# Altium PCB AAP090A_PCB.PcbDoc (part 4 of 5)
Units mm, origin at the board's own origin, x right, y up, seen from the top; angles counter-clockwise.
Board outline 160 x 130 mm, 4 copper layers (Top Layer, Signal Layer 1, Signal Layer 2, Bottom Layer), stack 1.567 mm thick; 507 components, 275 nets, 1462 pads, 1041 vias.
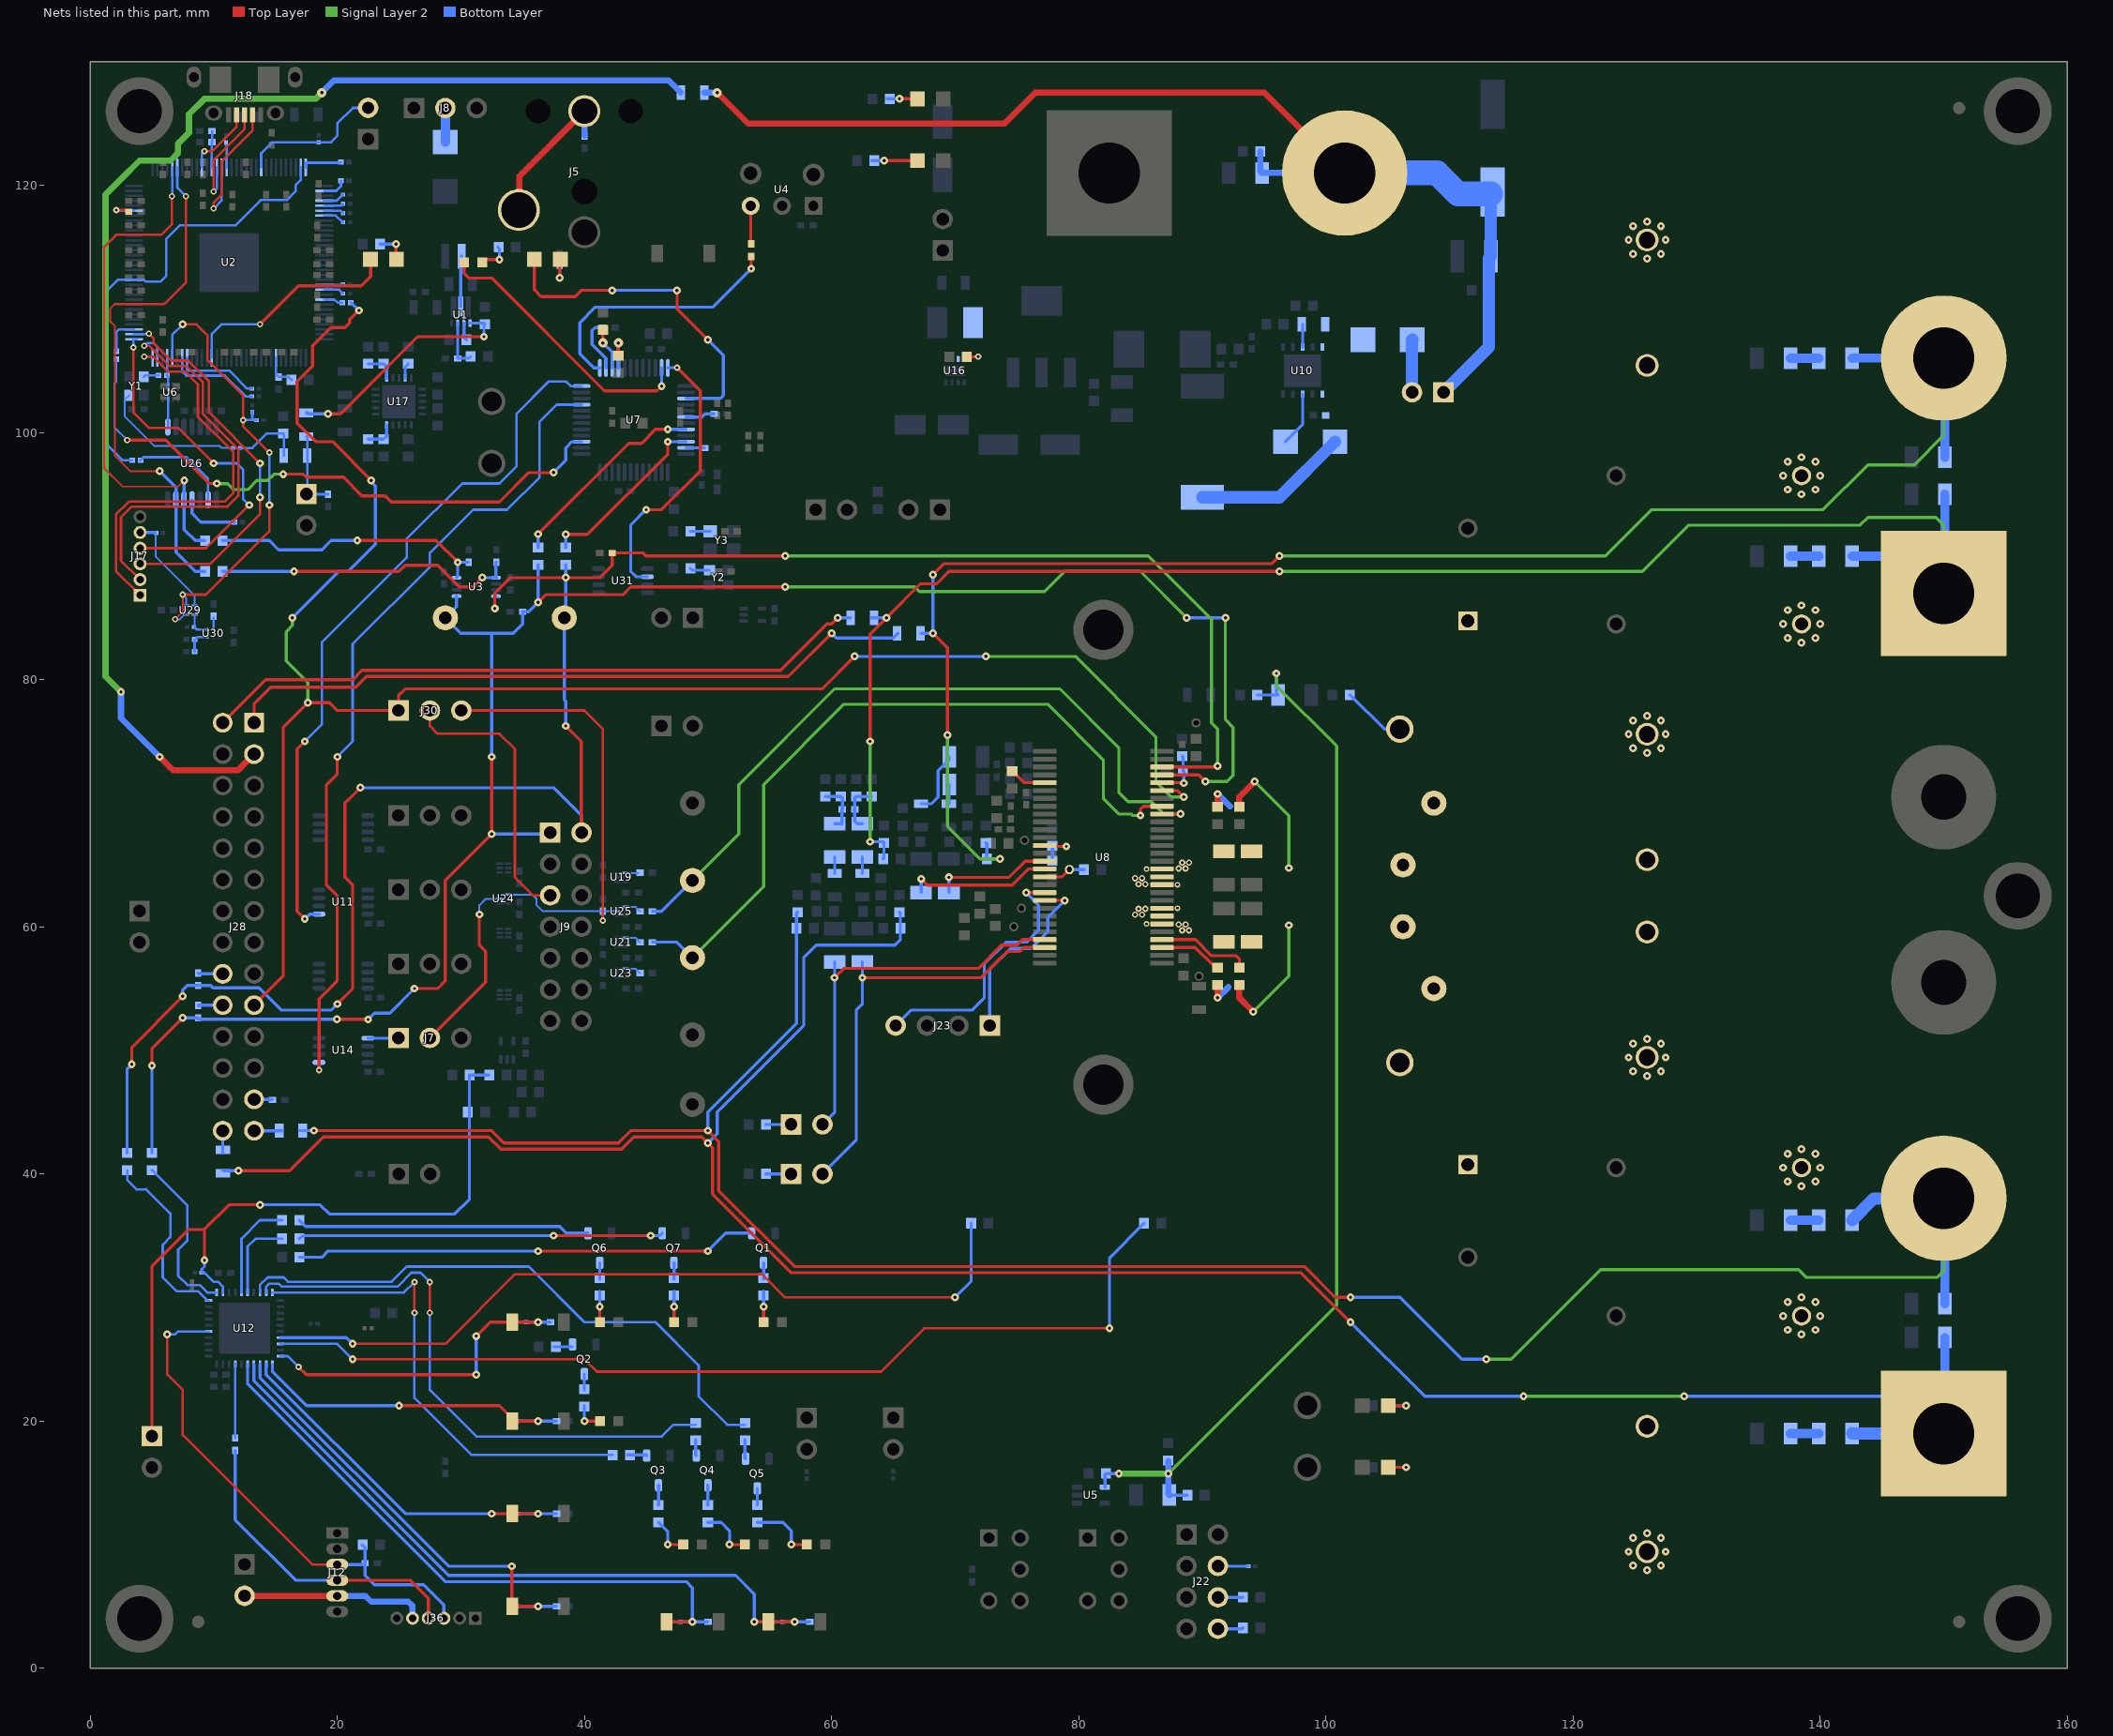
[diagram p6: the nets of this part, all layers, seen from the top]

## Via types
v1: diameter 0.635, hole 0.254, Top Layer to Bottom Layer, tented both sides, 653 vias
v2: diameter 0.508, hole 0.254, Top Layer to Bottom Layer, tented both sides, 340 vias
v3: diameter 0.5, hole 0.2, Top Layer to Bottom Layer, 24 vias
v4: diameter 0.6, hole 0.3, Top Layer to Bottom Layer, 12 vias
v5: diameter 0.762, hole 0.254, Top Layer to Bottom Layer, tented both sides, 8 vias
v6: diameter 0.457, hole 0.203, Top Layer to Bottom Layer, tented both sides, 4 vias

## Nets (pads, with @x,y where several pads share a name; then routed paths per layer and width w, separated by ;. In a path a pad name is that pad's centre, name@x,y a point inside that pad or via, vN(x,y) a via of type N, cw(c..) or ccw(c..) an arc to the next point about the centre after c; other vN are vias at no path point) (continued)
NetC76_2: C76.2 U8.32 | length 7.7
  Top Layer w0.25: U8.32@86.75,58.957 89.443,58.957 90.75,57.65 92.75,57.65 93,57.4 C76.2@93,56.6
NetC77_2: C77.2 U8.31 | length 5
  Top Layer w0.25: U8.31@86.75,58.322 89.427,58.322 91,56.75 C77.2@91,56.65
NetC82_1: C82.1 R140.2 U2.103 | length 2.8
  Bottom Layer w0.2: U2.103@15.05,106.05 15.05,104.7 C82.1@15.25,104.5 16.05,104.5 R140.2@16.3,104.25
NetC95_2: C95.2 U17.19 | length 1.3
  Bottom Layer w0.2: U17.19@25.5,104.4 25.5,105.3 C95.2@25.75,105.55
NetC98_1: C98.1 R87.2 | length 2.3
  Bottom Layer w0.75: R87.2@137.6,106 C98.1@139.9,106
NetC103_1: C103.1 R89.2 | length 2.3
  Bottom Layer w0.75: R89.2@137.6,90 C103.1@139.9,90
NetC104_1: C104.1 R93.2 | length 2.3
  Bottom Layer w0.75: R93.2@137.6,36.25 C104.1@139.9,36.25
NetC105_1: C105.1 R94.2 | length 2.3
  Bottom Layer w0.75: R94.2@137.6,19 C105.1@139.9,19
NetC106_1: C106.1 R13.1 R59.2 R67.2 | length 4
  Bottom Layer w0.25: R13.1@62.5,68.35 62.1,68.35 61.875,68.575 C106.1@61.875,69.5 61.875,70.425 R67.2@62,70.55 R59.2@63.25,70.55
NetC106_2: C106.2 R30.1 R64.2 R69.2 | length 4.1
  Bottom Layer w0.25: R64.2@59.5,70.55 R69.2@60.75,70.55 60.875,70.425 C106.2@60.875,69.5 60.85,69.475 60.85,68.35 R30.1@60.25,68.35
NetC107_2: C107.2 U8.5 | length 2.8
  Top Layer w0.25: C107.2@74.75,72.5 75.593,71.657 U8.5@77.25,71.657
NetC150_2: C150.2 U30.5 | length 1
  Bottom Layer w0.2: U30.5@10,84.05 C150.2@10,85
NetD1_1: D1.1 R141.2 | length 2.6
  Top Layer w0.25: v1(24.75,115.25) 24.75,114.05 D1.1@24.8,114
  Bottom Layer w0.25: R141.2@23.45,115.25 v1(24.75,115.25)
NetD1_2: D1.2 U2.116 | length 18.1
  Top Layer w0.25: v2(13.75,108.75) 16.875,111.875 21.95,111.875 22.7,112.625 D1.2@22.7,114
  Bottom Layer w0.2: U2.116@9.85,106.05 9.85,107.975 10.625,108.75 v2(13.75,108.75)
NetD2_1: D2.1 R19.2 | length 2.5
  Top Layer w0.25: D2.1@31.75,113.75 32,114 v1(33.125,114)
  Bottom Layer w0.25: R19.2@33,115 33.125,114.875 v1(33.125,114)
NetD2_2: D2.2 U7.11 | length 22.6
  Top Layer w0.25: D2.2@30.25,113.75 30.25,112.875 30.625,112.5 32.5,112.5 41.625,103.375 45.875,103.375 v1(46.25,103.75) ; D2.2@30.25,114 D2.2@30.375,113.875
  Bottom Layer w0.25: v1(46.25,103.75) U7.11@46.25,105.225
NetD3_1: D3.1 R23.1 | length 2.5
  Top Layer w0.25: v1(38,112.5) 38,113.95 D3.1@38.05,114
  Bottom Layer w0.25: v1(38,112.5) R23.1@38,113.5
NetD3_2: D3.2 U7.15 | length 27.7
  Top Layer w0.25: D3.2@36,113.95 D3.2@35.95,114 35.95,111.55 36.5,111 39.25,111 39.75,111.5 v1(42.25,111.5) ; v1(47.5,111.5) 47.5,110 v1(50,107.5)
  Bottom Layer w0.25: v1(42.25,111.5) v1(47.5,111.5) ; U7.15@48.225,102.75 51,102.75 51.25,103 51.25,106.25 v1(50,107.5)
NetD4_2: D4.2 R46.1 | length 2.5
  Top Layer w0.25: v1(40,20) D4.2@41.25,20
  Bottom Layer w0.25: v1(40,20) R46.1@40,21.25
NetD5_2: D5.2 R47.1 | length 3.4
  Top Layer w0.25: v1(46.75,10) D5.2@48,10
  Bottom Layer w0.25: R47.1@46,11.8 46.75,11.05 v1(46.75,10)
NetD6_2: D6.2 R48.1 | length 4.4
  Top Layer w0.25: v1(51.75,10) D6.2@53,10
  Bottom Layer w0.25: R48.1@50,11.8 51.075,11.8 51.75,11.125 v1(51.75,10)
NetD7_2: D7.2 R49.1 | length 5.4
  Top Layer w0.25: v1(56.75,10) D7.2@58,10
  Bottom Layer w0.25: R49.1@54,11.8 56.075,11.8 56.75,11.125 v1(56.75,10)
NetD8_2: D8.2 R57.1 | length 2.5
  Top Layer w0.25: D8.2@41.25,28 v1(41.25,29.25)
  Bottom Layer w0.25: v1(41.25,29.25) R57.1@41.25,30.5
NetD9_1: D9.1 R78.1 | length 2.7
  Top Layer w0.25: D9.1@105.05,21.25 v1(106.5,21.25)
  Bottom Layer w0.25: R78.1@105.2,21.25 v1(106.5,21.25)
NetD10_1: D10.1 R79.1 | length 2.7
  Top Layer w0.25: D10.1@105.05,16.25 v1(106.5,16.25)
  Bottom Layer w0.25: R79.1@105.2,16.25 v1(106.5,16.25)
NetD11_2: D11.2 J26.2 | length 4.3
  Bottom Layer w1: J26.2@106.98,103.25 106.98,107.48 D11.2@107,107.5
NetD12_2: D12.2 U10.3 | length 4.4
  Bottom Layer w0.25: D12.2@96.75,99.25 98.125,100.625 U10.3@98.125,103.1
NetD13_2: D13.2 R85.1 | length 2.5
  Top Layer w0.25: v1(65.5,127) D13.2@66.95,127
  Bottom Layer w0.25: R85.1@64.5,127 v1(65.5,127)
NetD14_2: D14.2 R86.1 | length 3.7
  Top Layer w0.25: v1(64.25,122) D14.2@66.95,122
  Bottom Layer w0.25: R86.1@63.25,122 v1(64.25,122)
NetD15_2: D15.2 R108.1 | length 2.5
  Top Layer w0.25: D15.2@47.25,28 v1(47.25,29.25)
  Bottom Layer w0.25: v1(47.25,29.25) R108.1@47.25,30.5
NetD16_2: D16.2 R106.1 | length 2.5
  Top Layer w0.25: D16.2@54.5,28 v1(54.5,29.25)
  Bottom Layer w0.25: v1(54.5,29.25) R106.1@54.5,30.5
NetD17_2: D17.2 J8.2 | length 2.7
  Bottom Layer w0.75: D17.2@28.75,123.5 J8.2@28.75,126.25
NetJ5_1: J5.1 J5.4 L4.1 | length 11.9
  Top Layer w0.5: J5.4@34.75,118 34.75,120.75 J5.1@40,126
  Bottom Layer w0.5: L4.1@40,124 J5.1@40,125.75
NetJ11_2: J11.2 J12.5 J36.5 | length 14.9
  Top Layer w0.5: J11.2@12.5,5.855 12.51,5.845 J12.5@20,5.845
  Bottom Layer w0.5: J12.5@20,5.845 22.28,5.845 22.75,5.375 25.75,5.375 26.095,5.03 J36.5@26.095,4.04
NetJ22_4: J22.4 R77.2 | length 2.5
  Bottom Layer w0.25: J22.4@91.27,8.27 91.29,8.25 R77.2@93.72,8.25
NetJ22_6: J22.6 R76.2 | length 2
  Bottom Layer w0.25: J22.6@91.27,5.73 93.28,5.73 R76.2@93.3,5.75
NetJ22_8: J22.8 R75.2 | length 2.1
  Bottom Layer w0.25: J22.8@91.27,3.19 93.24,3.19 R75.2@93.3,3.25
NetJ28_25: J28.25 R123.1 | length 1.5
  Bottom Layer w0.25: J28.25@13.27,46.03 14.72,46.03 R123.1@14.75,46
NetJ31_1: J31.1 R99.2 | length 2
  Bottom Layer w0.25: R99.2@54.7,44 J31.1@56.73,44
NetJ32_1: J32.1 R100.2 | length 2
  Bottom Layer w0.25: R100.2@54.7,40 J32.1@56.73,40
NetJ33_1: J33.1 R80.2 R159.2 R164.1 | length 6.5
  Bottom Layer w0.2: J33.1@17.5,94.875 17.575,94.95 J33.1@17.575,95 ; R159.2@17.5,99.675 17.575,99.6 R164.1@17.575,98.125 J33.1@17.575,95 ; R80.2@19.25,95 J33.1@17.575,95
NetL1_1: L1.1 U1.6 | length 4.1
  Bottom Layer w0.25: U1.6@30,110.2 30,114.175 L1.1@30.075,114.25
NetQ1_1: Q1.1 R109.1 | length 37.4
  Top Layer w0.25: v1(36.25,33.75) v1(50,33.75)
  Bottom Layer w0.25: R109.1@16.95,33.25 18.75,33.25 19.25,33.75 v1(36.25,33.75) ; v1(50,33.75) 51.45,35.2 Q1.1@53.55,35.2
NetQ1_3: Q1.3 R106.2 | length 1.3
  Bottom Layer w0.25: R106.2@54.5,31.5 Q1.3@54.5,32.8
NetQ2_1: Q2.1 R50.1 | length 1.5
  Bottom Layer w0.25: R50.1@37.5,26 Q2.1@39,26
NetQ2_3: Q2.3 R46.2 | length 1.3
  Bottom Layer w0.25: R46.2@40,22.5 Q2.3@40,23.8
NetQ3_1: Q3.1 R51.1 | length 1.6
  Bottom Layer w0.25: R51.1@43.5,17.25 45,17.25 Q3.1@45.05,17.2
NetQ3_3: Q3.3 R47.2 | length 1.6
  Bottom Layer w0.25: R47.2@46,13.2 Q3.3@46,14.8
NetQ4_1: Q4.1 R52.1 | length 1.3
  Bottom Layer w0.25: R52.1@49,18.5 49,17.25 Q4.1@49.05,17.2
NetQ4_3: Q4.3 R48.2 | length 1.6
  Bottom Layer w0.25: R48.2@50,13.2 Q4.3@50,14.8
NetQ5_1: Q5.1 R53.1 | length 1.6
  Bottom Layer w0.25: R53.1@53,18.5 53,17 Q5.1@53.05,16.95
NetQ5_3: Q5.3 R49.2 | length 1.3
  Bottom Layer w0.25: R49.2@54,13.2 Q5.3@54,14.55
NetQ6_1: Q6.1 R105.1 | length 23.8
  Bottom Layer w0.25: R105.1@16.95,36.25 17.45,35.75 38,35.75 38.55,35.2 Q6.1@40.3,35.2
NetQ6_3: Q6.3 R57.2 | length 1.3
  Bottom Layer w0.25: R57.2@41.25,31.5 Q6.3@41.25,32.8
NetQ7_1: Q7.1 R107.1 | length 29.5
  Top Layer w0.25: v1(37.5,35) v1(45.375,35)
  Bottom Layer w0.25: R107.1@16.95,34.75 17.2,35 v1(37.5,35) ; v1(45.375,35) 46.1,35 Q7.1@46.3,35.2
NetQ7_3: Q7.3 R108.2 | length 1.3
  Bottom Layer w0.25: R108.2@47.25,31.5 Q7.3@47.25,32.8
NetR1_1: R1.1 R3.2 U1.3 | length 4
  Bottom Layer w0.2: U1.3@29.75,108.85 R1.1@29.75,106 30.65,106 R3.2@30.8,106.15
NetR2_1: R2.1 U1.2 | length 1.4
  Bottom Layer w0.25: U1.2@30.25,108.85 30.25,107.7 R2.1@30.45,107.5
NetR4_2: R4.2 U16.8 | length 2.1
  Top Layer w0.25: R4.2@71,106.125 v2(71.875,106.125)
  Bottom Layer w0.25: U16.8@70.75,105.95 71.2,105.95 71.375,106.125 v2(71.875,106.125)
NetR6_2: R6.2 R7.2 U17.16 | length 2.5
  Bottom Layer w0.25: R6.2@22.5,105.55 R7.2@23.75,105.55 24,105.3 U17.16@24,104.4
NetR8_2: R8.2 R9.2 U17.10 | length 2.5
  Bottom Layer w0.25: R8.2@22.5,99.45 R9.2@23.75,99.45 24,99.7 U17.10@24,100.6
NetR13_2: R13.2 R14.1 | length 1.3
  Bottom Layer w0.25: R14.1@62.5,64.325 R13.2@62.5,65.65
NetR16_1: R16.1 U4.3 | length 3.1
  Top Layer w0.25: U4.3@53.46,118.33 53.46,115.29 R16.1@53.5,115.25
NetR17_1: R17.1 U19.4 | length 1
  Bottom Layer w0.15: U19.4@43.34,64.35 44.35,64.35 R17.1@44.375,64.375
NetR18_1: R18.1 U21.4 | length 1.3
  Bottom Layer w0.15: U21.4@43.34,59.1 44.15,59.1 R18.1@44.5,58.75
NetR20_2: R20.2 U7.18 | length 2.4
  Bottom Layer w0.25: U7.18@48.225,101.25 49.5,101.25 49.75,101.5 R20.2@50.5,101.5
NetR21_1: R21.1 U23.4 | length 1.3
  Bottom Layer w0.15: U23.4@43.34,56.6 44.15,56.6 R21.1@44.5,56.25
NetR22_2: R22.2 U7.23 | length 1.5
  Bottom Layer w0.25: U7.23@48.225,98.75 R22.2@49.75,98.75
NetR24_1: R24.1 U25.4 | length 1.3
  Bottom Layer w0.15: U25.4@43.34,61.6 44.15,61.6 R24.1@44.5,61.25
NetR30_2: R30.2 R33.1 | length 1.3
  Bottom Layer w0.25: R33.1@60.25,64.325 R30.2@60.25,65.65
NetR34_2: R34.2 U10.8 | length 1.9
  Bottom Layer w0.25: U10.8@98.125,106.9 R34.2@98.125,108.75
NetR61_2: R61.2 R68.1 | length 5.2
  Bottom Layer w0.25: R68.1@67.25,69.95 68.075,69.95 68.625,70.5 68.625,72.625 69.525,73.525 R61.2@69.525,73.75
NetR63_2: R63.2 R159.1 U1.1 | length 19.2
  Top Layer w0.25: v1(19.25,101.5) 20.25,101.5 20.375,101.625 21.375,102.625 26.5,107.75 v1(31.875,107.75)
  Bottom Layer w0.2: v1(31.875,107.75) 31.875,108.675 R63.2@31.95,108.75
  Bottom Layer w0.25: R159.1@17.5,101.575 17.55,101.625 17.675,101.5 v1(19.25,101.5) ; U1.1@30.75,108.85 R63.2@31.85,108.85
NetR72_2: R72.2 R73.1 | length 1.6
  Bottom Layer w0.25: R73.1@69.5,69.95 69.525,69.975 R72.2@69.525,71.5
NetR83_2: R83.2 U2.88 | length 1.6
  Bottom Layer w0.2: U2.88@18.95,110.75 19.75,110.75 20.058,110.5 R83.2@20.42,110.5
NetR101_2: R101.2 R102.2 U8.13 | length 4.1
  Top Layer w0.25: U8.13@77.25,66.577 77.328,66.5 v1(79,66.5)
  Bottom Layer w0.25: R102.2@77.875,65.325 77.875,66.5 v1(79,66.5)
NetR103_1: R103.1 U12.27 | length 64.5
  Top Layer w0.2: v1(21.25,26.25) 28.75,26.25 34.375,31.875 54.375,31.875 56.25,30 v1(70,30)
  Bottom Layer w0.25: U12.27@15.4,26.75 20.75,26.75 v1(21.25,26.25) ; v1(70,30) 71.3,31.3 R103.1@71.3,36
NetR104_1: R104.1 U12.28 | length 79.1
  Top Layer w0.2: v1(21.25,25) 40,25 41,24 64,24 67.5,27.5 v1(82.5,27.5)
  Bottom Layer w0.2: U12.28@15.4,26.25 20,26.25 v1(21.25,25)
  Bottom Layer w0.25: v1(82.5,27.5) 82.5,33.2 R104.1@85.3,36
NetR110_2: R110.2 U2.27 | length 2.5
  Top Layer w0.2: v2(2.125,118) 3,118 R110.2@3.125,117.875
  Bottom Layer w0.2: v2(2.125,118) 2.175,117.95 U2.27@3.55,117.95
NetR124_1: R124.1 R134.2 U3.8 | length 22.6
  Top Layer w0.25: v1(21.625,91.25) 28,91.25 v1(29.75,89.5)
  Bottom Layer w0.25: R134.2@10.7,91.25 14.5,91.25 15.25,90.5 18.75,90.5 19.5,91.25 v1(21.625,91.25) ; U3.8@29.65,88.25 29.75,88.35 v1(29.75,89.5) R124.1@30.625,89.5
NetR130_1: R130.1 Y2.3 | length 1.6
  Bottom Layer w0.25: R130.1@48.575,89 48.725,88.85 Y2.3@50.125,88.85
NetR131_1: R131.1 Y3.3 | length 1.6
  Bottom Layer w0.25: R131.1@48.575,92 Y3.3@50.175,92
NetR133_1: R133.1 R135.2 U3.1 | length 24.7
  Top Layer w0.25: v1(16.5,88.75) 25,88.75 25.5,89.25 28.125,89.25 29.875,87.5 31,87.5 v1(31.75,88.25)
  Bottom Layer w0.25: R135.2@10.7,88.75 v1(16.5,88.75) ; v1(31.75,88.25) U3.1@32.85,88.25 ; U3.1@32.875,88.225 U3.1@32.85,88.25 ; R133.1@32.875,89.5 32.85,89.475 U3.1@32.85,88.25
NetR136_1: R136.1 U2.68 | length 1.7
  Bottom Layer w0.2: U2.68@18.95,118.75 19.956,118.75 20.456,119.25 R136.1@20.47,119.25
NetR137_1: R137.1 U2.69 | length 1.6
  Bottom Layer w0.2: U2.69@18.95,118.35 20.32,118.35 R137.1@20.47,118.5
NetR138_1: R138.1 U2.70 | length 1.6
  Bottom Layer w0.2: U2.70@18.95,117.95 20.27,117.95 R138.1@20.47,117.75
NetR139_1: R139.1 U2.71 | length 1.7
  Bottom Layer w0.2: U2.71@18.95,117.55 19.887,117.55 20.437,117 R139.1@20.47,117
NetR142_2: R142.2 U2.64 | length 3.2
  Bottom Layer w0.2: U2.64@17.45,121.45 17.45,121.825 20.245,121.825 R142.2@20.295,121.875
NetR143_2: R143.2 U2.66 | length 2
  Bottom Layer w0.2: U2.66@18.95,119.55 19.925,119.55 20.295,119.92 R143.2@20.295,120.375
NetR146_2: R146.2 U2.3 | length 3.1
  Bottom Layer w0.2: R146.2@2.125,106.58 2.125,108.125 2.35,108.35 U2.3@3.55,108.35
NetR148_2: R148.2 U2.48 | length 1.8
  Bottom Layer w0.2: 11,123.25 11.05,123.2 U2.48@11.05,121.45
NetR151_2: R151.2 U26.11 | length 4.8
  Bottom Layer w0.25: U26.11@8.25,94.55 8.25,93.45 8.95,92.75 R151.2@11.67,92.75 R151.2@11.7,92.75
NetR152_2: R152.2 U26.9 | length 8.1
  Bottom Layer w0.2: R152.2@4,97.75 R152.2@4.08,97.75 4.33,98 7.8,98 9.55,96.25 U26.9@9.55,94.55
NetR153_1: R153.1 Y1.3 | length 1.2
  Bottom Layer w0.2: Y1.3@4.35,104.5 4.475,104.625 R153.1@5.545,104.625
NetR154_2: R154.2 Y1.1 | length 11.7
  Bottom Layer w0.15: Y1.1@3.15,103 2.8,102.65 2.8,101.3 5.2,98.9 10.5,98.9 10.65,98.75 R154.2@11.595,98.75
  Bottom Layer w0.2: R154.2@11.595,98.75 R154.2@11.625,98.75
NetR155_2: R155.2 U29.3 U30.4 | length 2.2
  Bottom Layer w0.15: R155.2@8.465,84.26 U29.3@8.465,85.275
  Bottom Layer w0.2: R155.2@8.465,84.26 8.455,84.25 8.655,84.05 U30.4@9.5,84.05
NetR156_2: R156.2 R158.1 U30.3 | length 2.1
  Bottom Layer w0.2: R158.1@8.455,82.25 8.455,83.205 8.7,83.45 U30.3@9.5,83.45
NetR160_2: R160.2 U2.85 | length 1.5
  Bottom Layer w0.2: U2.85@18.95,111.95 20.42,111.95 R160.2@20.47,112
NetR161_2: R161.2 U2.86 | length 1.6
  Bottom Layer w0.2: U2.86@18.95,111.55 20.156,111.55 20.456,111.25 R161.2@20.47,111.25
NetR162_2: R162.2 U2.121 | length 6.8
  Bottom Layer w0.2: U2.121@7.85,106.05 7.85,105.113 7.963,105 11.25,105 12.705,103.545 R162.2@13.095,103.545
NetR163_2: R163.2 U2.122 | length 7.6
  Bottom Layer w0.2: U2.122@7.45,106.05 7.45,104.947 7.797,104.6 10.9,104.6 12.58,102.92 R163.2@13.095,102.92
NetR165_1: R165.1 R166.2 U8.52 | length 4
  Top Layer w0.25: U8.52@86.75,71.657 88.468,71.657 v1(88.5,71.625)
  Bottom Layer w0.25: R165.1@88.375,73.8 88.45,73.725 R166.2@88.45,72.625 88.5,72.575 v1(88.5,71.625)
OC_ADJ: R74.2 TP14.1 U8.17 | length 3.4
  Top Layer w0.25: U8.17@77.25,64.037 78.663,64.037 TP14.1@79.25,64.625
  Bottom Layer w0.25: TP14.1@79.25,64.625 R74.2@80.425,64.625
OPTICAL-LED: R107.2 U12.16 | length 6.8
  Bottom Layer w0.2: U12.16@12.75,30.4 12.75,34.125 13.375,34.75 R107.2@15.55,34.75
OSC-IOM: J23.4 U8.19 | length 21.3
  Top Layer w0.25: v1(75.75,62.75) 75.768,62.767 U8.19@77.25,62.767
  Bottom Layer w0.25: J23.4@65.19,52 66.44,53.25 71.375,53.25 72.36,54.235 72.36,56.985 74.125,58.75 75.793,58.75 76.75,59.707 76.75,61.75 v1(75.75,62.75)
OSC-IOP: J23.1 U8.20 | length 15.2
  Top Layer w0.25: U8.20@77.25,62.132 78.868,62.132 v1(78.875,62.125)
  Bottom Layer w0.25: J23.1@72.81,52 72.81,56.56 74.5,58.25 76.125,58.25 77.5,59.625 77.5,60.75 v1(78.875,62.125)
OUT_A+: J28.1 R125.2 | length 56.3
  Top Layer w0.25: J28.1@13.27,76.51 13.27,78.02 14.625,79.375 21.5,79.375 22.375,80.25 56.5,80.25 v1(60,83.75)
  Bottom Layer w0.25: v1(60,83.75) 60.375,83.375 65,83.375 R125.2@65.375,83.75
OUT_A-: J28.2 R126.2 | length 54.3
  Top Layer w0.25: J28.2@10.73,76.51 14.22,80 21.25,80 22,80.75 55.875,80.75 59.625,84.5 60,84.5 v1(60.5,85)
  Bottom Layer w0.25: v1(60.5,85) R126.2@61.55,85
OUT_B+: J28.27 R127.2 | length 2.3
  Bottom Layer w0.25: J28.27@13.27,43.49 15.54,43.49 R127.2@15.55,43.5
OUT_B-: J28.28 R128.2 | length 1.8
  Bottom Layer w0.25: J28.28@10.73,43.49 10.73,41.72 R128.2@10.75,41.7
OUTA+: C16.1 C47.1 C98.2 C152.2 J10.2 L5.2 R96.1 R125.1 | length 137.7
  Top Layer w0.25: v1(68.2,83.75) 69.375,82.575 v1(69.375,75.5) ; v1(68.2,88.5) 69.075,89.375 95.625,89.375 v1(96.25,90)
  Signal Layer 2 w0.25: v1(69.375,75.5) 69.375,68.125 72,65.5 v1(73.625,65.5) ; v1(96.25,90) 122.625,90 126.375,93.75 140.25,93.75 143.875,97.375 147.625,97.375 150,99.75 J10.2@150,106.025
  Bottom Layer w0.25: R125.1@67.25,83.75 v1(68.2,83.75) v1(68.2,88.5) ; C16.1@72.5,66.8 72.575,66.725 R96.1@72.575,65.5 v1(73.625,65.5)
  Bottom Layer w0.75: C98.2@142.6,106 142.625,106.025 J10.2@150,106.025 150.1,105.925 C152.2@150.1,98
  other v1: 138.5,95 137.375,95.375 139.625,95.375 137,96.5 140,96.5 137.375,97.625 139.625,97.625 138.5,98 126,114.075 124.875,114.45 127.125,114.45 124.5,115.575 127.5,115.575 124.875,116.7 127.125,116.7 126,117.075
OUTA-: C13.1 C67.1 C103.2 C153.2 J10.1 L6.2 R70.1 R126.1 | length 133.8
  Top Layer w0.25: v1@63.125,75.125 63.125,83.675 v1(64.45,85) 67.2,87.75 68.5,87.75 69.5,88.75 v1(96.25,88.75)
  Signal Layer 2 w0.25: v1@63.125,66.75 v1(63.125,66.875) v1(63.125,75) ; v1(96.25,88.75) 125.625,88.75 129.375,92.5 143.25,92.5 143.875,93.125 149.375,93.125 150,92.5 J10.1@150,86.975
  Bottom Layer w0.25: v1(63.125,66.875) 64.175,66.875 C13.1@64.25,66.8 64.25,65.575 R70.1@64.175,65.5 ; R126.1@63.2,85 R126.1@63.45,85 v1(64.45,85)
  Bottom Layer w0.75: C103.2@142.6,90 146.975,90 J10.1@150,86.975 150.1,87.075 C153.2@150.1,95
  other v1: 126,74.075 124.875,74.45 127.125,74.45 124.5,75.575 127.5,75.575 124.875,76.7 127.125,76.7 126,77.075 138.5,83 137.375,83.375 139.625,83.375 137,84.5 140,84.5 137.375,85.625 139.625,85.625 138.5,86
OUTB+: C10.1 C79.1 C104.2 C154.2 J15.2 L7.2 R35.1 R127.1 | length 190.7
  Top Layer w0.25: v1(18.125,43.5) 32.5,43.5 33.5,42.5 42.75,42.5 43.75,43.5 v1(50,43.5) 50.875,42.625 50.875,38.625 57,32.5 98.25,32.5 100.75,30 v1(102,30)
  Signal Layer 2 w0.25: v1(113,25) 115,25 122.25,32.25 138.25,32.25 138.875,31.625 149.5,31.625 150,32.125 J15.2@150,38.025
  Bottom Layer w0.25: R127.1@16.95,43.5 v1(18.125,43.5) ; v1(50,43.5) 50,45 57.175,52.175 R35.1@57.175,59.875 57.175,61.1 C10.1@57.25,61.175 ; v1(102,30) 106,30 111,25 v1(113,25)
  Bottom Layer w0.75: J15.2@150,38.025 150.1,37.925 C154.2@150.1,29.5
  Bottom Layer w1: C104.2@142.6,36.25 144.35,38 149.75,38 J15.2@150,37.75
  other v1: 138.5,39 137.375,39.375 139.625,39.375 137,40.5 140,40.5 137.375,41.625 139.625,41.625 138.5,42 126,47.925 124.875,48.3 127.125,48.3 124.5,49.425 127.5,49.425 124.875,50.55 127.125,50.55 126,50.925
OUTB-: C7.1 C81.1 C105.2 C155.2 J15.1 L8.2 R15.1 R128.1 | length 199.7
  Top Layer w0.25: v1(12,40.25) 16.125,40.25 18.875,43 32.25,43 33.25,42 43,42 44,43 49.5,43 v1(50,42.5) 50.375,42.125 50.375,38.375 56.75,32 98,32 v1(102,28) ; J15.1@147.25,16 J15.1@150.25,19
  Signal Layer 2 w0.25: v1(116,22) v1(129,22)
  Bottom Layer w0.25: R128.1@10.75,40.3 10.8,40.25 v1(12,40.25) ; v1(50,42.5) 50.75,43.25 50.75,45 57.75,52 57.75,57.5 58.75,58.5 65.125,58.5 65.575,58.95 R15.1@65.575,59.875 65.575,61.1 C7.1@65.5,61.175 ; v1(102,28) 108,22 v1(116,22) ; v1(129,22) 146.25,22 J15.1@148.375,19.875
  Bottom Layer w0.75: J15.1@150,18.975 150.1,19.075 C155.2@150.1,26.75
  Bottom Layer w1: C105.2@142.6,19 142.625,18.975 J15.1@150,18.975
  other v1: 126,7.925 124.875,8.3 127.125,8.3 124.5,9.425 127.5,9.425 124.875,10.55 127.125,10.55 126,10.925 138.5,27 137.375,27.375 139.625,27.375 137,28.5 140,28.5 137.375,29.625 139.625,29.625 138.5,30
P0-LED: R53.2 U12.18 | length 47.5
  Bottom Layer w0.2: U12.18@13.75,30.4 13.75,31 14.375,31.625 15.65,31.625 16,31.275 24.4,31.275 25.625,32.5 35.5,32.5 40,28 45.75,28 49.25,24.5 49.25,22 51.55,19.7 R53.2@53,19.7
P1-LED: R52.2 U12.19 | length 46.9
  Top Layer w0.2: v2(27.5,28.75) v2(27.5,31.25)
  Bottom Layer w0.2: U12.19@14.25,30.4 14.25,30.875 14.5,31.125 15.25,31.125 15.5,30.875 24.875,30.875 26,32 26.75,32 v2(27.5,31.25) ; v2(27.5,28.75) 27.5,22.5 31.25,18.75 46.25,18.75 47.2,19.7 R52.2@49,19.7
P2-LED: R51.2 U12.20 | length 39.2
  Top Layer w0.2: v2(26.25,28.75) v2(26.25,31.25)
  Bottom Layer w0.2: U12.20@14.75,30.4 25.4,30.4 v2(26.25,31.25) ; v2(26.25,28.75) 26.25,21.875 30.875,17.25 R51.2@42.3,17.25
PVDD: C23.1 C25.1 C28.2 C29.2 C30.1 C31.1 C32.2 C33.1 C41.2 C42.2 C43.1 J24.2 J26.1 R28.2 R32.2 TP7.1 TP8.1 U8.35 U8.40 | length 100.4
  Top Layer w0.5: v5(50.75,127.5) 53.25,125 74,125 76.5,127.5 95.025,127.5 J24.2@101.525,121
  Bottom Layer w0.25: R32.2@101.95,78.75 102,78.75 104.75,76 TP7.1@106,76
  Bottom Layer w0.5: R28.2@49.7,127.5 v5(50.75,127.5) ; C33.1@94.7,122.75 94.7,121.15 C32.2@94.85,121 J24.2@101.525,121
  Bottom Layer w1: J26.1@109.52,103.25 113.2,106.93 C25.1@113.2,111.5 113.2,114.1 C23.1@113.35,114.25 C31.1@113.35,119.3
  Bottom Layer w2: J24.2@101.525,121 109,121 110.7,119.3 C31.1@113.35,119.3
PVDD-EXT: J28.3 R28.1 | length 108
  Top Layer w0.5: v1(5.625,73.75) 6.695,72.68 11.98,72.68 J28.3@13.27,73.97
  Signal Layer 2 w0.5: v1(2.5,79) 1.25,80.25 1.25,119.25 2.625,120.625 4,122 6.5,122 7.125,122.625 7.125,123.375 8,124.25 8,125.75 9.25,127 18.25,127 v5(18.75,127.5)
  Bottom Layer w0.5: v1(2.5,79) 2.5,76.875 v1(5.625,73.75) ; v5(18.75,127.5) 19.75,128.5 46.8,128.5 R28.1@47.8,127.5
RX1+: R16.2 U7.1 | length 21.3
  Top Layer w0.25: v1(53.5,113.25) R16.2@53.5,114.25
  Bottom Layer w0.25: U7.1@41.25,105.225 40.775,105.225 39.625,106.375 39.625,108.875 40.893,110.143 50.393,110.143 v1(53.5,113.25)
RX1-: C19.2 U7.2 | length 4.5
  Bottom Layer w0.25: C19.2@41.5,108.5 40.875,108.5 40.625,108.25 40.625,107.125 41.75,106 U7.2@41.75,105.225
RX2+: C20.1 U7.3 | length 3.4
  Top Layer w0.25: v5(41.5,107.25) C20.1@41.5,108.3
  Bottom Layer w0.25: v5(41.5,107.25) 42.25,106.5 U7.3@42.25,105.225
RX2-: C21.1 U7.4 | length 3.1
  Top Layer w0.25: C21.1@42.75,106.2 v5(42.75,107.25)
  Bottom Layer w0.25: v5(42.75,107.25) U7.4@42.75,105.225 U7.4@42.775,105.2
RXCKO: U7.12 U31.2 | length 22.6
  Top Layer w0.25: v1(45,93.75) 46.25,93.75 49.375,96.875 49.375,103.375 v2(47.5,105.25)
  Bottom Layer w0.25: v1(45,93.75) 43.75,92.5 43.75,88.75 44.175,88.325 U31.2@45.1,88.325 ; U7.12@46.75,105.225 46.775,105.25 v2(47.5,105.25)
SBWTCK: R43.1 U12.37 | length 6
  Bottom Layer w0.2: R43.1@11.75,18.625 U12.37@11.75,24.6
SBWTDIO: C52.2 J12.3 J36.3 R41.1 U12.5 | length 42.3
  Top Layer w0.2: v1(6.25,27) 6.25,23.75 7.5,22.5 7.5,18.875 17.99,8.385 J12.3@20,8.385
  Bottom Layer w0.2: v1(6.25,27) 6.875,27 7.125,27.25 U12.5@9.6,27.25
  Bottom Layer w0.25: J12.3@20,8.385 22.135,8.385 R41.1@22.25,8.5 ; C52.2@22,10 22.25,9.75 R41.1@22.25,8.5 ; J36.3@28.635,4.04 28.635,5.115 27,6.75 23,6.75 22.25,7.5 R41.1@22.25,8.5
SCL: J9.1 R26.2 R54.1 R81.1 R170.1 TP21.1 U3.5 U8.53 | length 161.6
  Top Layer w0.25: v1(5,48.75) 5,50.125 v1(7.5,52.625) ; v1(19.975,52.525) 22.475,52.525 v1(22.5,52.5) ; v1(26.25,55) 28.125,55 28.75,55.625 28.75,63.75 v1(32.5,67.5) v1(32.5,73.75) ; v1(36.25,86.25) 36.875,86.875 43.125,86.875 43.75,87.5 v1(56.25,87.5) ; U8.53@86.75,72.292 89.707,72.292 v1(90.25,71.75)
  Signal Layer 2 w0.25: v1(56.25,87.5) 66.75,87.5 67.125,87.125 77.25,87.125 78.875,88.75 85,88.75 v1(88.75,85) ; v1(90.25,71.75) 92,71.75 92.5,72.25 92.5,76.125 91.875,76.75 v1(91.875,85)
  Bottom Layer w0.25: R54.1@5,41.7 v1(5,48.75) ; v1(7.5,52.625) R26.2@8.75,52.625 8.75,52.525 v1(19.975,52.525) ; v1(22.5,52.5) 23,53 24.25,53 v1(26.25,55) ; U3.5@29.65,86.75 29.65,85.9 TP21.1@28.75,85 30,83.75 32.5,83.75 ; v1(32.5,67.5) 37.11,67.5 J9.1@37.23,67.62 ; v1(32.5,73.75) 32.5,83.75 ; R170.1@36.25,89.3 v1(36.25,86.25) 35.5,85.5 R81.1@35,85.5 35,84.5 34.25,83.75 32.5,83.75 ; v1(88.75,85) v1(91.875,85)
SCL-AIB: J28.20 R26.1 | length 2
  Bottom Layer w0.25: R26.1@8.75,53.625 8.775,53.65 J28.20@10.73,53.65
SCL-MCU: R54.2 U12.11 | length 13.7
  Bottom Layer w0.2: R54.2@5,40.3 7.875,37.425 7.875,34.625 7.125,33.875 7.125,31.75 7.875,31 8.875,31 9.475,30.4 U12.11@10.25,30.4
SCL-SRC: R170.2 U7.20 | length 16.6
  Top Layer w0.25: v1(36.25,91.778) 43.597,99.125 44.625,99.125 45.75,100.25 v1(46.75,100.25)
  Bottom Layer w0.25: R170.2@36.25,90.7 v1(36.25,91.778) ; v1(46.75,100.25) U7.20@48.225,100.25
SCLK: R18.2 TP3.1 U8.49 | length 61.3
  Top Layer w0.25: v1(85,69) 85,69.5 85.252,69.752 U8.49@86.75,69.752
  Signal Layer 2 w0.25: TP3.1@48.75,57.5 54.5,63.25 54.5,71.5 61,78 77.5,78 82,73.5 82,70.375 83.25,69.125 84.25,69.125 84.375,69 v1(85,69)
  Bottom Layer w0.25: R18.2@45.5,58.75 47.5,58.75 TP3.1@48.75,57.5
SCLK-SRC: U7.48 U11.1 | length 58.1
  Top Layer w0.25: v1(17.375,60.625) 16.75,61.25 16.75,74.375 v1(17.375,75)
  Bottom Layer w0.2: v1(17.375,75) 18.75,76.375 18.75,83 25.625,89.875 25.625,91.375 30.125,95.875 33.125,95.875 34.5,97.25 34.5,101.5 37.125,104.125 38.5,104.125 38.875,103.75 U7.48@39.775,103.75
  Bottom Layer w0.25: v1(17.375,60.625) 17.775,61.025 U11.1@18.525,61.025
SDA: J9.2 R27.2 R55.1 R82.1 R169.1 TP22.1 U3.4 U8.54 | length 171.5
  Top Layer w0.25: v1(3.375,48.875) 3.375,50.25 v1(7.5,54.375) ; v1(20,53.75) 21.25,55 21.25,63.375 20.625,64 20.625,70 21.375,70.75 v1(21.875,71.25) ; v1(32.75,85.75) 32.75,87 34,88.25 v1(38.5,88.25) 41.25,88.25 42.25,89.25 R82.1@42.25,90.25 44.75,90.25 45,90 v1(56.25,90) ; v1(38.5,76.25) 39.75,75 J9.2@39.75,67.625 ; U8.54@86.75,72.927 91.178,72.927 v1(91.25,73) 91.355,73 91.428,72.927 v1@91.25,72.927
  Signal Layer 2 w0.25: v1(56.25,90) 85.625,90 90.75,84.875 90.75,76.5 91.25,76 v1(91.25,73)
  Bottom Layer w0.25: R55.1@3,41.7 3,48.5 v1(3.375,48.875) ; v1(7.5,54.375) 7.5,54.875 7.875,55.25 R27.2@8.75,55.25 9.75,55.25 9.935,55.065 13.685,55.065 15.5,53.25 19.5,53.25 v1(20,53.75) ; v1(21.875,71.25) 37.5,71.25 39.77,68.98 J9.2@39.77,67.62 ; v1(32.75,85.75) 32.75,86.65 U3.4@32.85,86.75 ; v1(38.5,76.25) 38.5,78.25 38.375,78.375 TP22.1@38.375,85 38.5,85.125 v1(38.5,88.25) R169.1@38.5,89.3
SDA-AIB: J28.18 R27.1 | length 2
  Bottom Layer w0.25: R27.1@8.75,56.25 8.81,56.19 J28.18@10.73,56.19
SDA-MCU: R55.2 U12.10 | length 15.3
  Bottom Layer w0.2: R55.2@3,40.3 3,39.5 3.75,38.75 4.5,38.75 ; 4.525,38.775 6.5,36.8 6.5,34.875 5.875,34.25 5.875,31.625 7,30.5 8.75,30.5 9.5,29.75 U12.10@9.6,29.75
SDA-SRC: R169.2 U7.22 | length 14.5
  Top Layer w0.25: v1(38.5,91.75) 40.25,91.75 46.75,98.25 v1(46.75,99.25)
  Bottom Layer w0.25: R169.2@38.5,90.7 v1(38.5,91.75) ; v1@46.75,99.125 46.875,99.25 U7.22@48.225,99.25
SDIN: R24.2 TP1.1 U8.48 | length 60.4
  Top Layer w0.25: U8.48@86.75,69.117 88.242,69.117 v1(88.25,69.125)
  Signal Layer 2 w0.25: TP1.1@48.75,63.75 52.5,67.5 52.5,71.5 60.25,79.25 78.5,79.25 83.25,74.5 83.25,70.875 84,70.125 85.875,70.125 86.875,69.125 v1(88.25,69.125)
  Bottom Layer w0.25: R24.2@45.5,61.25 46.25,61.25 TP1.1@48.75,63.75
SDIN-BUF: J30.3 R118.2 U24.4 U25.2 | length 38
  Top Layer w0.2: J30.3@30.04,77.5 40,77.5 41.5,76 v2(41.5,60.5)
  Bottom Layer w0.15: U24.4@33.84,62.6 35.775,62.6 36.125,62.25 36.125,61.75 36.625,61.25 R118.2@41.5,61.25 U25.2@42.66,61.25
  Bottom Layer w0.2: v2(41.5,60.5) R118.2@41.5,61.25
SDIN-IBC: J9.5 J30.2 | length 22.7
  Top Layer w0.2: J30.2@27.5,77.5 27.5,76.25 28.125,75.625 33.125,75.625 34.375,74.375 34.375,64 35.835,62.54 J9.5@37.23,62.54
SDIN-MUX: J7.1 U14.5 | length 2.5
  Bottom Layer w0.25: U14.5@22.475,50.975 24.935,50.975 J7.1@24.96,51
SDIN-PSIA: J7.2 U24.2 | length 14.7
  Top Layer w0.25: J7.2@27.5,51 32,55.5 32,58 31.5,58.5 v1(31.5,61)
  Bottom Layer w0.15: v1(31.5,61) 31.5,61.75 32,62.25 U24.2@33.16,62.25
SDOUT: J28.19 J30.1 R83.1 U8.51 | length 151.6
  Top Layer w0.25: J28.19@13.27,53.65 15.625,56.005 15.625,76.125 v1(17.625,78.125) 19.375,78.125 20,77.5 J30.1@24.96,77.5 24.96,78.71 25.5,79.25 59.25,79.25 v1(61.875,81.875) ; U8.51@86.75,71.022 87.978,71.022 v1(88.5,70.5)
  Top Layer w0.254: v1(21.75,109.875) 21,109.125 21,108.875 20.625,108.5 19.5,108.5 18,107 18,105.375 16.75,104.125 16.75,100.75 18.25,99.25 19.625,99.25 v1(22.75,96.125)
  Signal Layer 2 w0.25: v1(72.5,81.875) 79.75,81.875 86.25,75.375 86.25,71.75 87.5,70.5 v1(88.5,70.5)
  Signal Layer 2 w0.254: v1(16.375,85) 16.375,84.375 15.875,83.875 15.875,81.5 17.625,79.75 v1(17.625,78.125)
  Bottom Layer w0.25: v1(61.875,81.875) v1(72.5,81.875)
  Bottom Layer w0.254: v1(16.375,85) 20.125,88.75 20.875,88.75 23.083,90.958 23.083,95.667 v1@22.75,96 ; R83.1@21.125,110.5 v1(21.75,109.875)
SDOUT-SRC: U7.45 U14.1 | length 66.8
  Top Layer w0.25: v2(18.525,48.4) 18.525,54.15 20,55.625 20,62.5 19.125,63.375 19.125,71.5 20,72.375 v1(20,73.75)
  Bottom Layer w0.2: v1(20,73.75) 21.25,75 21.25,82.875 27.5,89.125 27.5,90.25 31,93.75 33.75,93.75 36.375,96.375 36.375,100.875 37.75,102.25 U7.45@39.775,102.25
  Bottom Layer w0.25: v2(18.525,48.4) U14.1@18.525,49.025
SDOUT-USB: R146.1 U7.39 | length 49.5
  Top Layer w0.25: v2(3,99.375) 6.125,99.375 9.625,95.875 v1(10.25,95.875) ; v1(15.625,96.625) 17.25,96.625 17.375,96.5 17.5,96.375 20.5,96.375 22,94.875 23.875,94.875 24.375,94.375 33.125,94.375 35.5,96.75 v1(37.5,96.75)
  Signal Layer 2 w0.25: v1(10.25,95.875) 10.268,95.857 11.143,95.857 11.625,95.375 12.75,95.375 13.5,96.125 14.375,96.125 14.875,96.625 v1(15.625,96.625)
  Bottom Layer w0.15: R146.1@2.125,105.92 2.125,104.125 1.95,103.95 1.95,100.425 v2(3,99.375)
  Bottom Layer w0.25: v1(37.5,96.75) 38.5,97.75 38.5,98.75 39,99.25 U7.39@39.775,99.25
SLAVE-EN: J35.1 R10.2 R112.2 R113.2 R114.1 U12.12 | length 60.2
  Top Layer w0.25: J35.1@5,18.77 5,32.5 8,35.5 9.25,35.5 ; v1(9.25,33) 9.25,35.5 ; v1(13.75,37.5) 11.25,37.5 9.25,35.5
  Bottom Layer w0.2: v1(9.25,33) 9.25,32.5 9.03,32.28 R114.1@9.03,32 9.25,32 10,31.25 10.375,31.25 10.75,30.875 U12.12@10.75,30.4
  Bottom Layer w0.25: v1(13.75,37.5) 18.625,37.5 19.375,36.75 29.5,36.75 30.7,37.95 R112.2@30.7,48 R113.2@32.25,48
SPK_INA+: C14.2 U8.15 | length 9.5
  Top Layer w0.25: v1(69.5,64) 74.375,64 75.683,65.307 U8.15@77.25,65.307
  Bottom Layer w0.25: C14.2@69.5,62.775 v1(69.5,64)
SPK_INA-: C11.2 U8.16 | length 11.9
  Top Layer w0.25: v1(67.25,63.875) 67.768,63.357 74.607,63.357 75.922,64.672 U8.16@77.25,64.672
  Bottom Layer w0.25: C11.2@67.25,62.775 v1(67.25,63.875)
SPK_INB+: C8.2 J31.2 U8.25 | length 33.1
  Top Layer w0.25: v1(60.25,55.875) 61,56.625 71.875,56.625 73.75,58.5 75,58.5 75.457,58.957 U8.25@77.25,58.957
  Bottom Layer w0.25: J31.2@59.27,44 60.25,44.98 60.25,45.75 C8.2@60.25,57.15 v1(60.25,55.875)
SPK_INB-: C5.2 J32.2 U8.26 | length 34.3
  Top Layer w0.25: v1(62.5,55.875) 72.125,55.875 74.25,58 75.25,58 75.572,58.322 U8.26@77.25,58.322
  Bottom Layer w0.25: J32.2@59.27,40 62,42.73 62,53.25 62.5,53.75 v1(62.5,55.875) C5.2@62.5,57.15
SPK_OUTA+: C66.1 L5.1 TP17.1 U8.41 | length 2.5
  Top Layer w0.5: C66.1@91.25,69.7 v1(91.25,70.75)
  Bottom Layer w0.5: v1(91.25,70.75) 92.25,69.75
  other v2: 88.1,64.72 88.65,64.72 88.375,65.195 88.925,65.195
  other v6: 85.5,64.67
SPK_OUTA-: C68.1 L6.1 TP18.1 U8.39 | length 10.7
  Top Layer w0.5: C68.1@93,69.75 93,70.5 v1(94.25,71.75)
  Signal Layer 2 w0.25: v1(94.25,71.75) 97,69 v1(97,64.75)
  Bottom Layer w0.25: v2(84.575,63.925) v2@84.575,64
  other v2: 84.85,63.45 85.4,63.45 85.125,63.925
  other v6: 88,63.4
SPK_OUTB+: C76.1 L7.1 TP19.1 U8.36 | length 10.8
  Top Layer w0.5: C76.1@93,55.3 93,54.25 v1(94.125,53.125)
  Signal Layer 2 w0.25: v1(94.125,53.125) 97,56 v1(97,60.125)
  other v2: 84.575,60.975 85.125,60.975 84.85,61.45 85.4,61.45
  other v6: 88,61.5
SPK_OUTB-: C77.1 L8.1 TP20.1 U8.34 | length 2.4
  Top Layer w0.5: v1(91.25,54.25) C77.1@91.25,55.3 C77.1@91.25,55.375
  Bottom Layer w0.5: v1(91.25,54.25) 92.125,55.125
  other v2: 88.375,59.705 88.925,59.705 88.1,60.18 88.65,60.18
  other v6: 85.5,60.23
SW: L3.1 U16.7
SW-INPUT: C57.1 R38.2 S9.2 U12.30 | length 27
  Top Layer w0.25: v2(16.875,24.375) 17.5,23.75 v1(31.25,23.75) ; v1(31.25,26.875) 32.375,28 S9.2@34.15,28 v1(36.25,28)
  Bottom Layer w0.2: U12.30@15.4,25.25 16,25.25 v2(16.875,24.375)
  Bottom Layer w0.25: v1(31.25,23.75) v1(31.25,26.875) ; R38.2@35.28,28 v1(36.25,28) C57.1@37.25,28
SW-LOAD: C53.1 R45.2 S8.2 U12.35 | length 51.5
  Top Layer w0.25: S8.2@46.65,3.75 v1(48.75,3.75)
  Bottom Layer w0.25: U12.35@12.75,24.6 12.75,23 28.75,7 48.25,7 48.75,6.5 v1(48.75,3.75) ; R45.2@47.78,3.75 v1(48.75,3.75) ; C53.1@50,3.75 v1(48.75,3.75)
SW-MUTE: C48.1 R39.2 S4.2 U12.31 | length 26.9
  Top Layer w0.25: v1(25,21.25) 33.125,21.25 34.15,20.225 S4.2@34.15,20 v1(36.25,20)
  Bottom Layer w0.25: U12.31@14.75,24.6 14.75,24 17.5,21.25 v1(25,21.25) ; 34.75,20 v1(36.25,20) C48.1@37.75,20
SW-PROGSEL: C51.1 R44.2 S7.2 U12.34 | length 56.7
  Top Layer w0.25: v1(53.75,3.75) S7.2@54.9,3.75 v1(57,3.75)
  Bottom Layer w0.25: U12.34@13.25,24.6 13.25,23.25 29,7.5 52.25,7.5 53.75,6 v1(53.75,3.75) ; R44.2@56.03,3.75 v1(57,3.75) C51.1@58.25,3.75
SW-PS: C26.2 D12.1 L9.1 U10.1 | length 12.6
  Bottom Layer w1: L9.1@90,94.75 96.25,94.75 D12.1@100.75,99.25
SW-VOLDN: C50.1 R42.2 S6.2 U12.33 | length 36.2
  Top Layer w0.25: v1(34.125,8.25) 34.125,5.225 34.25,5.1 S6.2@34.15,5 v1(36.25,5)
  Bottom Layer w0.25: U12.33@13.75,24.6 13.75,23.5 29,8.25 v1(34.125,8.25) ; 34.75,5 C50.1@37.75,5
SW-VOLUP: C49.1 R40.2 S5.2 U12.32 | length 30.6
  Top Layer w0.25: v1(32.5,12.5) S5.2@34.15,12.5 v1(36.25,12.5)
  Bottom Layer w0.25: U12.32@14.25,24.6 14.25,23.75 25.5,12.5 v1(32.5,12.5) ; R40.2@34.655,12.5 v1(36.25,12.5) C49.1@37.75,12.5
TCK: J12.4 J36.4 R43.2 | length 25.5
  Top Layer w0.25: J12.4@20,7.115 25.885,7.115 27.365,5.635 J36.4@27.365,4.04
  Bottom Layer w0.25: R43.2@11.75,17.625 11.75,12 16.635,7.115 J12.4@20,7.115
USB-LED: R105.2 U12.15 | length 8.3
  Bottom Layer w0.2: U12.15@12.25,30.4 12.25,34.75 13.75,36.25 R105.2@15.55,36.25
USB_D_M: J18.2 U2.47 | length 12.5
  Top Layer w0.2: v2(10,118.125) 10,118.588 10.65,119.238 10.65,121.95 13.15,124.45 J18.2@13.15,125.7
  Bottom Layer w0.2: v2(10,118.125) 10.65,118.775 U2.47@10.65,121.45
USB_D_P: J18.3 U2.46 | length 9.3
  Top Layer w0.2: v2(10,119.5) 10.004,119.504 10.004,122.054 12.5,124.55 J18.3@12.5,125.7
  Bottom Layer w0.2: v2(10,119.5) 10.25,119.75 U2.46@10.25,121.45
USB_ID: J18.4 U2.43 | length 5.8
  Top Layer w0.2: v2(9.25,122.75) 9.875,122.75 11.85,124.725 J18.4@11.85,125.7
  Bottom Layer w0.2: U2.43@9.05,121.45 9.05,122.55 v2(9.25,122.75)
VBUS-XMOS: C141.1 R145.1 U2.45 | length 2.9
  Bottom Layer w0.2: U2.45@9.85,121.45 9.85,123.475 C141.1@9.875,123.5 R145.1@9.875,124.375
VDD-RST: C46.1 C64.1 C96.1 C97.2 R56.1 R60.2 U5.4 | length 86.3
  Signal Layer 2 w0.25: v1(87.25,15.75) 100.875,29.375 100.875,74.625 96,79.5 v1(96,80.5)
  Signal Layer 2 w0.5: v1(83.25,15.75) v1(87.25,15.75)
  Bottom Layer w0.25: U5.4@82.125,14.65 82.125,15.675 C96.1@82.2,15.75 v1(83.25,15.75) ; C97.2@87.35,14 R60.2@88.8,14 ; R56.1@94.45,78.75 C46.1@96.15,78.75 96,78.9 v1(96,80.5)
  Bottom Layer w0.5: C64.1@87.25,16.75 v1(87.25,15.75) 87.25,14.1 C97.2@87.35,14
VIN-PS: D11.1 R34.1 U10.10
X-24M: R153.2 U2.125 U6.2 | length 2.4
  Bottom Layer w0.2: U2.125@6.25,106.05 6.25,104.67 R153.2@6.205,104.625 6.3,104.53 U6.2@6.3,103.7
X-HS-EN: J16.2 R144.2 U2.55 | length 11.9
  Bottom Layer w0.2: U2.55@13.85,121.45 13.85,122.6 14.72,123.47 R144.2@18.5,123.47 19.5,123.47 ; 19.5,123.5 20,124 20,125 21.27,126.27 J16.2@22.5,126.27
X-MCLK: R152.1 U2.13 U2.63 | length 37.9
  Bottom Layer w0.2: R152.1@3.42,97.75 2.625,97.75 2.375,98 1.1,99.275 1.1,111.2 2.25,112.35 U2.13@3.55,112.35 4.37,112.35 4.524,112.196 5.696,112.196 6.15,112.65 6.15,115.65 7.25,116.75 11.75,116.75 13.8,118.8 15.925,118.8 16.625,119.5 16.625,120 17.05,120.425 U2.63@17.05,121.45
X-RSTN: R147.2 R150.2 U2.124 U29.4 U29.6 | length 38.7
  Top Layer w0.152: v2(6.875,84.875) 7.5,85.5 v2(7.5,86.875)
  Top Layer w0.2: v2(7.5,86.875) 9.375,86.875 14.5,92 v1(14.5,94.125) ; v1(7.5,108.75) 8.625,108.75 9.5,107.875 9.5,105.875 12.375,103 v2(12.375,101) 12.375,100.5 v2(14.5,98.375)
  Bottom Layer w0.15: v2(6.875,84.875) 7.25,84.875 7.65,85.275 U29.4@7.785,85.275 ; v2(7.5,86.875) 7.785,86.59 U29.6@7.785,85.975
  Bottom Layer w0.2: U2.124@6.65,106.05 6.65,107.9 v1(7.5,108.75) ; v2(12.375,101) 13.125,101 ; R147.2@13.125,101.72 R147.2@13.125,101.64 13.125,101 ; R150.2@13.5,101 R150.2@13.47,101 13.125,101 ; v1(14.5,94.125) v2(14.5,98.375)
X-SCL: R134.1 U2.37 U26.12 | length 42.1
  Top Layer w0.15: 1.125,115 1.125,97.125 2.625,95.625 7.125,95.625 v1(7.625,96.125)
  Top Layer w0.2: 1.125,115 2.125,116 5.75,116 6.625,116.875 v2(6.625,119.125)
  Bottom Layer w0.2: v2@6.65,119.15 U2.37@6.65,121.45
  Bottom Layer w0.25: v1@7.6,96.15 U26.12@7.6,94.55 7.6,92.15 8.5,91.25 R134.1@9.3,91.25
X-SDA: R135.1 U2.38 U26.13 | length 42.9
  Top Layer w0.15: 2,110.375 1.625,110 1.625,109 2,108.625 2,98.125 3.25,96.875 v1(5.625,96.875)
  Top Layer w0.2: 2,110.375 6,110.375 7.75,112.125 v2(7.75,119.125)
  Bottom Layer w0.2: U2.38@7.05,121.45 7.05,119.825 v2(7.75,119.125)
  Bottom Layer w0.25: v1(5.625,96.875) 6.95,95.55 U26.13@6.95,94.55 6.95,90.3 8.5,88.75 R135.1@9.3,88.75
X-TCK: J17.1 U2.128 | length 33.6
  Top Layer w0.2: J17.1@4.04,86.825 2.1,88.765 2.1,93.35 3.15,94.4 10.9,94.4 11.6,95.1 11.6,98.4 8.725,101.275 8.725,103.894 7.684,104.934 6.309,104.934 5.119,106.125 v2(4.375,106.125)
  Bottom Layer w0.2: v2(4.375,106.125) 5.05,106.125 U2.128@5.05,106.05
X-TDI: J17.3 U2.2 | length 31.8
  Top Layer w0.2: J17.3@4.04,89.365 9.74,89.365 13.75,93.375 v1(13.75,94.75) ; v2(4.75,108) 5.125,107.625 5.125,107.25 6.562,105.813 7.938,105.813 9.625,104.125 9.625,101.625 v1(13.75,97.5)
  Bottom Layer w0.2: U2.2@3.55,107.95 4.7,107.95 v2(4.75,108) ; v1(13.75,94.75) v1(13.75,97.5)
X-TDO: J17.4 U2.1 | length 30.3
  Top Layer w0.2: v2(3.5,106.875) 3.5,101.625 4.75,100.375 7.125,100.375 v1(10,97.5) ; J17.4@4.04,90.635 9.385,90.635 v1(12.875,94.125)
  Bottom Layer w0.2: v2(3.5,106.875) 3.5,107.55 U2.1@3.55,107.55 U2.1@3.75,107.55 ; v1(10,97.5) 11.875,97.5 12.375,97 12.375,94.625 v1(12.875,94.125)
X-TMS: J17.2 U2.127 | length 34.4
  Top Layer w0.2: J17.2@4,88.125 2.5,89.625 2.5,93.125 3.375,94 11.125,94 12,94.875 12,98.625 9.125,101.5 9.125,104.059 7.809,105.375 6.434,105.375 4.809,107 v2(4.375,107)
  Bottom Layer w0.2: v2(4.375,107) 4.625,107.25 5.125,107.25 5.45,106.925 U2.127@5.45,106.05
X-TRSTN: J17.5 R149.2 U29.1 | length 8.5
  Bottom Layer w0.15: R149.2@5.295,91.875 5.295,89.955 8.465,86.785 U29.1@8.465,85.975
  Bottom Layer w0.25: J17.5@4.04,91.905 5.265,91.905 R149.2@5.295,91.875
XIN-CLK: U6.7 U26.1 | length 2.3
  Bottom Layer w0.2: U26.1@6.3,100.45 U6.7@6.3,102.8
XMOS-ENABLE: R154.1 R164.2 R167.2 | length 5.8
  Bottom Layer w0.2: R154.1@12.125,98.75 R154.1@12.155,98.75 13.125,98.75 14.3,99.925 R167.2@15.625,99.925 ; R167.2@15.625,99.875 15.675,99.825 R164.2@15.675,98.125
pads on no net: FID1.1 FID2.1 FID3.1 FID4.1 FID5.1 FID6.1 H2. H3. H4. H5. H6.0 H7.0 H8.0 H9.0 H10. H11.0 J5.M1 J5.M2 J5.M3 J9.9 J9.13 J9.14 J12.1 J12.6 J18.M1 J18.M2 J28.5 J28.6 J28.23 J36.1 J36.6 S1.6 S3.6 SH1.0 SH2.0 SH3.0 SH4.0 SH5.0 SH6.0 SH7.0 SH8.0 SH9.0 SH10.0 SH11.0 SH12.0 SH13.0 SH14.0 SH15.0 SH16.0 SH17.0 SH18.0 SH19.0 SH20.0 SH21.0 SH22.0 U2.4 U2.5 U2.7 U2.8 U2.9 U2.10 U2.12 U2.15 U2.18 U2.20 U2.21 U2.22 U2.23 U2.25 U2.26 U2.28 U2.30 U2.31 U2.32 U2.33 U2.34 U2.35 U2.39 U2.40 U2.50 U2.51 U2.53 U2.54 U2.57 U2.58 U2.59 U2.61 U2.62 U2.65 U2.72 U2.74 U2.75 U2.76 U2.77 U2.79 U2.82 U2.84 U2.89 U2.90 U2.91 U2.93 U2.94 U2.95 U2.96 U2.97 U2.98 U2.99 U2.100 U2.106 U2.107 U2.108 U2.109 U2.112 U2.113 U2.114 U2.115 U2.117 U2.118 U2.119 U5.1 U6.6 U7.5 U7.6 U7.7 U7.8 U7.13 U7.26 U7.27 U7.28 U7.29 U7.31 U7.32 U7.34 U7.35 U7.36 U7.40 U7.41 U7.46 U9.3 U11.3 U12.26 U12.29 U12.36 U12.41@11.13,26.13 U12.41@11.13,27.5 U12.41@11.13,28.87 U12.41@12.5,26.13 U12.41@12.5,27.5 U12.41@12.5,28.87 U12.41@13.87,26.13 U12.41@13.87,27.5 U12.41@13.87,28.87 U13.3 U14.3 U17.9 U17.17 U17.21@24.305,101.805 U17.21@24.305,103.195 U17.21@25.695,101.805 U17.21@25.695,103.195 U18.5 U19.5 U20.5 U21.5 U22.5 U23.5 U24.5 U25.5 U26.4 U26.8 U26.14 U27.1 U28.1 U31.3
